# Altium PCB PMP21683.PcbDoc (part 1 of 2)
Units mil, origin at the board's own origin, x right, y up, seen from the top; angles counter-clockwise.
Board outline 4950 x 3450 mil, 2 copper layers (Top Layer, Bottom Layer), stack 62 mil thick; 134 components, 57 nets, 365 pads, 111 vias.
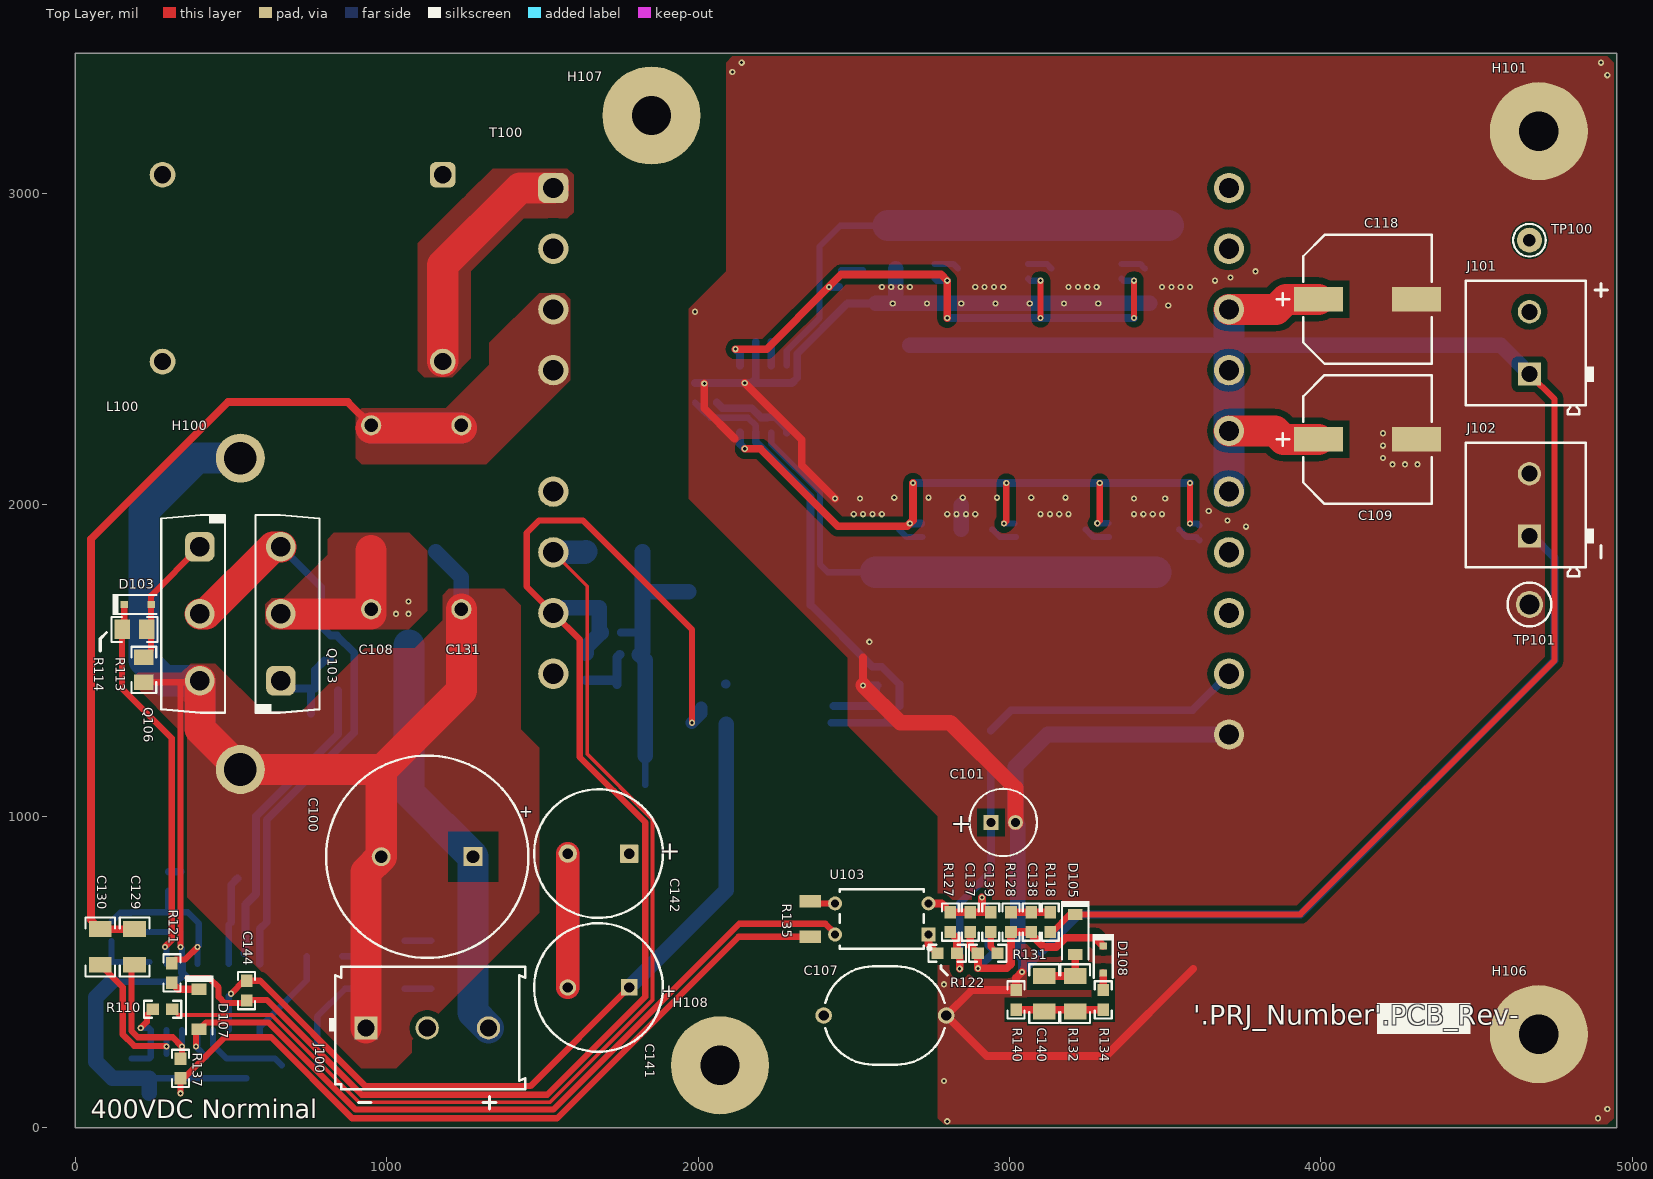
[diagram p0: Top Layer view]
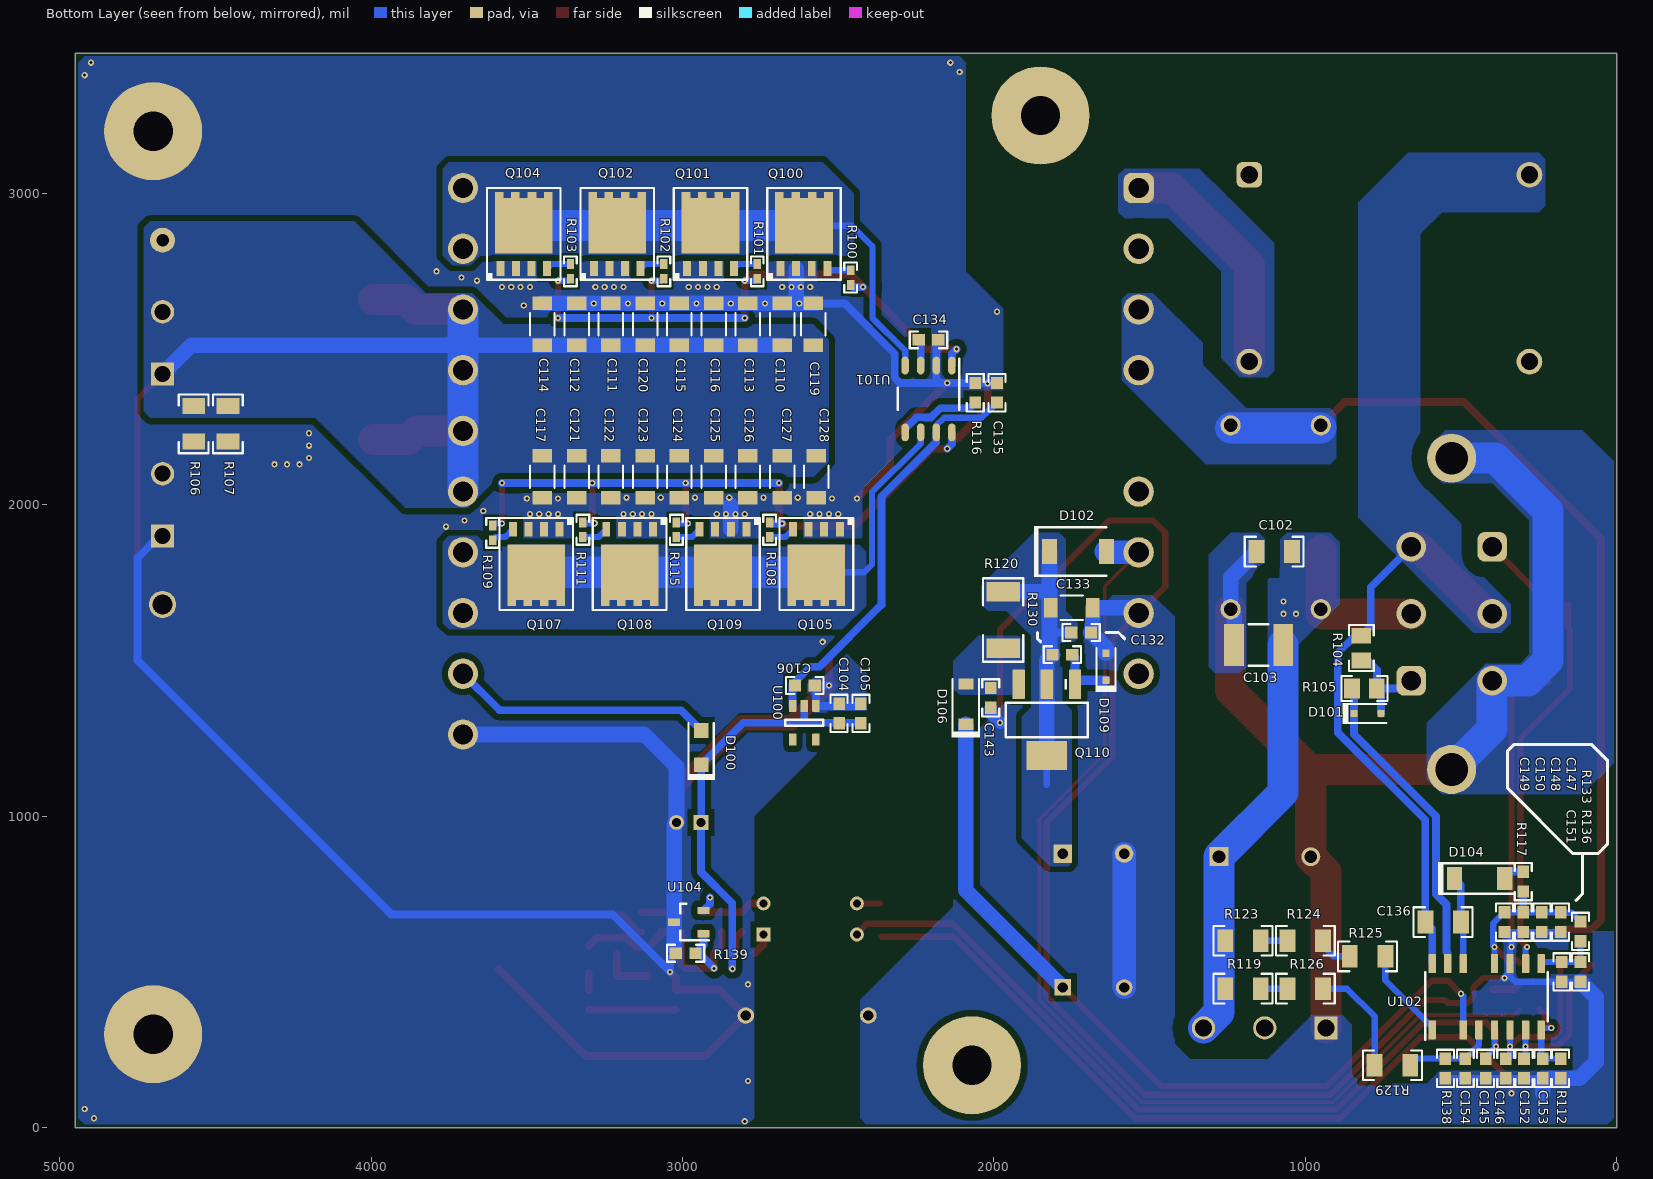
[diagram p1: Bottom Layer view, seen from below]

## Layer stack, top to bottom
Top Solder: solder mask 0.4, Solder Resist, Dk 3.5
Top Layer: signal copper 1.4
Dielectric1: core 59.2, FR-4, Dk 4.8
Bottom Layer: signal copper 1.4
Bottom Solder: solder mask 0.4, Solder Resist, Dk 3.5

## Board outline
0,0 4950,0 4950,3450 0,3450

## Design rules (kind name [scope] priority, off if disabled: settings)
AcuteAngle [All] p1: minimum=4.50000000000000E+0001 checktracksonly=FALSE
AssemblyTestPointUsage [All] p1: valid=2
Clearance Clearance_3 [InNet('GND') vs InNet('SGND')] p1: gap=236 ignorepadtopadclearanceinfootprint=FALSE
Clearance Clearance_2 [InNetClass('HV') vs Not InNetClass('HV')] p2: gap=50 ignorepadtopadclearanceinfootprint=FALSE except(0: Arc-Hole Track-Hole SMDPad-Hole THPad-Hole Via-Hole Fill-Hole Poly-Hole Region-Hole Text-Hole)
Clearance Clearance_1 [InNetClass('MV') vs Not InNetClass('MV')] p3: gap=30 ignorepadtopadclearanceinfootprint=FALSE
Clearance Clearance_Keepouts [((IsTrack Or IsArc) And Not InPoly) And IsFree and IsKeepOut vs ((IsTrack Or IsArc) And Not InPoly) And IsFree and IsKeepOut] p4: gap=0 ignorepadtopadclearanceinfootprint=FALSE
Clearance Clearance_BoardEdge_MountingHoles [OnCopper and InComponentClass('Mounting Holes') vs IsKeepOut] p5: gap=40 ignorepadtopadclearanceinfootprint=FALSE except(0: Arc-Hole Track-Hole SMDPad-Hole THPad-Hole Via-Hole Fill-Hole Poly-Hole Region-Hole Text-Hole)
Clearance Clearance_BoardEdge_Poly [OnCopper and InPoly vs IsKeepOut] p6: gap=25 ignorepadtopadclearanceinfootprint=FALSE except(0: Arc-Hole Track-Hole SMDPad-Hole THPad-Hole Via-Hole Fill-Hole Poly-Hole Region-Hole Text-Hole)
Clearance Clearance_BoardEdge [OnCopper and Not InComponentClass('Logo') and not InComponentClass('FiducialMark') and not InRegion(1000,500,4000,800) and Not IsKeepout vs IsKeepOut] p7: gap=75 ignorepadtopadclearanceinfootprint=FALSE except(0: Arc-Hole Track-Hole SMDPad-Hole THPad-Hole Via-Hole Fill-Hole Poly-Hole Region-Hole Text-Hole)
Clearance Clearance_Poly [InPolygon] p8: gap=20 ignorepadtopadclearanceinfootprint=FALSE except(0: Arc-Hole Track-Hole SMDPad-Hole THPad-Hole Via-Hole Fill-Hole Poly-Hole Region-Hole Text-Hole)
Clearance [All] p9: gap=7.87 ignorepadtopadclearanceinfootprint=FALSE except(0: Arc-Hole Track-Hole SMDPad-Hole THPad-Hole Via-Hole Fill-Hole Poly-Hole Region-Hole Text-Hole)
ComponentClearance ComponentClearance_MountingHoles_FiducialMarks [InComponentClass('Mounting Holes') vs InComponentClass('FiducialMark')] p1: gap=20 collisioncheckmode=3 verticalgap=10 showdistances=FALSE
ComponentClearance ComponentClearance_Shunt [InComponentClass('Header') vs InComponentClass('Shunt')] p2: gap=0 collisioncheckmode=3 verticalgap=0 showdistances=FALSE
ComponentClearance ComponentClearance_Logo [InComponentClass('Logo')] p3: gap=5 collisioncheckmode=3 verticalgap=10 showdistances=FALSE
ComponentClearance ComponentClearance_ScrewToNut [(HasFootprint('NY PMS 440 0025 PH')) vs (HasFootprint('Keystone_1902C'))] p4: gap=20 collisioncheckmode=3 verticalgap=100000 showdistances=FALSE
ComponentClearance ComponentClearance_MountingHoles [InComponentClass('Mounting Holes')] p5: gap=20 collisioncheckmode=3 verticalgap=10 showdistances=FALSE
ComponentClearance ComponentClearance_SmallPassives [HasFootprint('0201*') or HasFootprint('0402*') or HasFootprint('0508') or HasFootprint('0603*') or HasFootprint('0612') or HasFootprint('0805*') or HasFootprint('0815*') or HasFootprint('0830*') or HasFootprint('1206*') or HasFootprint('1210*') or HasFootprint('1808*') or HasFootprint('1812*') or HasFootprint('1825*') or HasFootprint('2010*') or HasFootprint('2220*') or HasFootprint('2225*') or HasFootprint('2512*') or HasFootprint('2728*') or HasFootprint('3518*') vs HasFootprint('0201*') or HasFootprint('0402*') or HasFootprint('0508') or HasFootprint('0603*') or HasFootprint('0612') or HasFootprint('0805*') or HasFootprint('0815*') or HasFootprint('0830*') or HasFootprint('1206*') or HasFootprint('1210*') or HasFootprint('1808*') or HasFootprint('1812*') or HasFootprint('1825*') or HasFootprint('2010*') or HasFootprint('2220*') or HasFootprint('2225*') or HasFootprint('2512*') or HasFootprint('2728*') or HasFootprint('3518*')] p6: gap=20 collisioncheckmode=3 verticalgap=20 showdistances=FALSE
ComponentClearance ComponentClearance_THtoSMT [IsThruComponent vs IsSMTComponent] p7: gap=10 collisioncheckmode=3 verticalgap=10 showdistances=FALSE
ComponentClearance ComponentClearance_THtoTH [IsThruComponent vs IsThruComponent] p8: gap=10 collisioncheckmode=3 verticalgap=10 showdistances=FALSE
ComponentClearance [All] p9: gap=10 collisioncheckmode=3 verticalgap=10 showdistances=FALSE
DiffPairsRouting [All] p1: maxlimit=100 minlimit=10 mostfreqgap=10 toplayer_minwidth=15 toplayer_maxwidth=15 toplayer_prefwidth=15 bottomlayer_minwidth=15 bottomlayer_maxwidth=15 bottomlayer_prefwidth=15 maxuncoupledlength=1000
FabricationTestPointUsage TestPointUsage [All] p1: valid=2 allowmultiple=FALSE
FabricationTestpoint Testpoint [All] p1: side=3 testpointundercomponent=TRUE minsize=40 maxsize=100 preferedsize=60 minholesize=0 maxholesize=40 preferedholesize=32 testpointgrid=1 allowsidetop=TRUE allowsidebottom=TRUE usegrid=TRUE gridtolerance=0.01
FanoutControl Fanout_LCC [IsLCC] p1: bgadir=Out bgaviamode=Centered fanoutstyle=Auto fanoutdirection=Alternating viagrid=1 // Fanout_LCC (Default Rule)
FanoutControl Fanout_BGA [IsBGA] p2: bgadir=Out bgaviamode=Centered fanoutstyle=Auto fanoutdirection=Alternating viagrid=1 // Fanout_BGA (Default Rule)
FanoutControl Fanout_Default [All] p4: bgadir=Out bgaviamode=Centered fanoutstyle=Auto fanoutdirection=Alternating viagrid=1 // Fanout_Default (Default Rule)
FanoutControl Fanout_Small [(CompPinCount < 5)] p5: bgadir=Out bgaviamode=Centered fanoutstyle=Auto fanoutdirection=OutThenIn viagrid=1 // Fanout_Small (Default Rule)
Height [All] p1: minheight=0 maxheight=3000 prefheight=500
HoleSize [All] p1: absolutevalues=TRUE maxlimit=251 minlimit=7 maxpercent=80.000 minpercent=20.000
MinimumAnnularRing MinimumAnnularRing_ThermalPadVias [IsVia and InAnyComponent] p1: minimumring=5.91
MinimumAnnularRing [All] p2: minimumring=4.9
MinimumSolderMaskSliver MinimumSolderMaskSliver_Logo [InComponentClass('Logo') vs InComponentClass('Logo')] p1: minsoldermaskwidth=0.7
MinimumSolderMaskSliver [All] p2: minsoldermaskwidth=2
PlaneConnect [All] p1: planeconnectstyle=Direct reliefexpansion=10 reliefentries=4 reliefconductorwidth=10 reliefairgap=10
PolygonConnect PolygonConnect_17 [All vs IsNamedPolygon('SGND') Or  IsNamedPolygon('VD_SR2') Or  IsNamedPolygon('SGND') Or  IsNamedPolygon('VD_SR1') Or  IsNamedPolygon('Vout') Or  IsNamedPolygon('C141_2') Or  IsNamedPolygon('VCC') Or  IsNamedPolygon('Vin') Or  IsNamedPolygon('L100_4') Or  IsNamedPolygon('C108_2') Or  IsNamedPolygon('L100_4') Or  IsNamedPolygon('HS') Or  IsNamedPolygon('Vin')] p1: connectstyle=Direct reliefconductorwidth=10 reliefentries=4 polygonreliefangle="90 Angle" airgapwidth=10
PolygonConnect PolygonConnect_16 [All vs IsNamedPolygon('HS') Or  IsNamedPolygon('L100_4') Or  IsNamedPolygon('Vin1') Or  IsNamedPolygon('C108_2') Or  IsNamedPolygon('Vin') Or  IsNamedPolygon('VCC') Or  IsNamedPolygon('C141_2') Or  IsNamedPolygon('L100_4') Or  IsNamedPolygon('Vin')] p2: connectstyle=Direct reliefconductorwidth=10 reliefentries=4 polygonreliefangle="90 Angle" airgapwidth=10
PolygonConnect PolygonConnect_15 [All vs IsNamedPolygon('C109_2') Or  IsNamedPolygon('C107_2') Or  IsNamedPolygon('HV') Or  IsNamedPolygon('Q203_5') Or  IsNamedPolygon('C107_2') Or  IsNamedPolygon('HS') Or  IsNamedPolygon('Q201_5') Or  IsNamedPolygon('Q203_5') Or  IsNamedPolygon('C106_2') Or  IsNamedPolygon('C108_2') Or  IsNamedPolygon('Vout') Or  IsNamedPolygon('Q203_5') Or  IsNamedPolygon('C108_2') Or  IsNamedPolygon('C113_2') Or  IsNamedPolygon('Q203_5') Or  IsNamedPolygon('Q201_5') Or  IsNamedPolygon('C107_2') Or  IsNamedPolygon('C102_1') Or  IsNamedPolygon('SGND') Or  IsNamedPolygon('GND') Or  IsNamedPolygon('SGND') Or  IsNamedPolygon('GND') Or  IsNamedPolygon('IN+') Or  IsNamedPolygon('IN+') Or  IsNamedPolygon('Q201_5') Or  IsNamedPolygon('Q201_5') Or  IsNamedPolygon('SGND') Or  IsNamedPolygon('SGND') Or  IsNamedPolygon('Vout') Or  IsNamedPolygon('Vout') Or  IsNamedPolygon('IN+') Or  IsNamedPolygon('GND') Or  IsNamedPolygon('IN+') Or  IsNamedPolygon('GND')] p3: connectstyle=Direct reliefconductorwidth=10 reliefentries=4 polygonreliefangle="90 Angle" airgapwidth=10
PolygonConnect PolygonConnect_14 [All vs IsNamedPolygon('C106_2') Or  IsNamedPolygon('C107_2') Or  IsNamedPolygon('C107_2') Or  IsNamedPolygon('C107_2') Or  IsNamedPolygon('C102_1') Or  IsNamedPolygon('Q203_5') Or  IsNamedPolygon('Vout') Or  IsNamedPolygon('Q203_5') Or  IsNamedPolygon('Q203_5') Or  IsNamedPolygon('Q201_5') Or  IsNamedPolygon('C108_2') Or  IsNamedPolygon('Q203_5') Or  IsNamedPolygon('HS') Or  IsNamedPolygon('HV') Or  IsNamedPolygon('C108_2') Or  IsNamedPolygon('Q201_5') Or  IsNamedPolygon('C109_2') Or  IsNamedPolygon('Q201_5') Or  IsNamedPolygon('Q201_5') Or  IsNamedPolygon('C113_2')] p4: connectstyle=Direct reliefconductorwidth=10 reliefentries=4 polygonreliefangle="90 Angle" airgapwidth=10
PolygonConnect PolygonConnect_13 [All vs IsNamedPolygon('C102_1') Or  IsNamedPolygon('HV') Or  IsNamedPolygon('C107_2') Or  IsNamedPolygon('C109_2') Or  IsNamedPolygon('C107_2') Or  IsNamedPolygon('C108_2') Or  IsNamedPolygon('C106_2') Or  IsNamedPolygon('C108_2') Or  IsNamedPolygon('C113_2') Or  IsNamedPolygon('C107_2')] p5: connectstyle=Direct reliefconductorwidth=10 reliefentries=4 polygonreliefangle="90 Angle" airgapwidth=10
PolygonConnect PolygonConnect_12 [All vs IsNamedPolygon('C107_2') Or  IsNamedPolygon('C113_2') Or  IsNamedPolygon('C106_2') Or  IsNamedPolygon('C107_2') Or  IsNamedPolygon('C107_2') Or  IsNamedPolygon('C102_1')] p6: connectstyle=Direct reliefconductorwidth=10 reliefentries=4 polygonreliefangle="90 Angle" airgapwidth=10
PolygonConnect PolygonConnect_11 [All vs IsNamedPolygon('C106_2') Or  IsNamedPolygon('C102_1') Or  IsNamedPolygon('C107_2') Or  IsNamedPolygon('C107_2') Or  IsNamedPolygon('C107_2')] p7: connectstyle=Direct reliefconductorwidth=10 reliefentries=4 polygonreliefangle="90 Angle" airgapwidth=10
PolygonConnect PolygonConnect_10 [All vs IsNamedPolygon('C106_2')] p8: connectstyle=Direct reliefconductorwidth=10 reliefentries=4 polygonreliefangle="90 Angle" airgapwidth=10
PolygonConnect PolygonConnect_9 [All vs IsNamedPolygon('C11_1') Or  IsNamedPolygon('Vin') Or  IsNamedPolygon('Vin') Or  IsNamedPolygon('5V') Or  IsNamedPolygon('D6_2') Or  IsNamedPolygon('Q3_3') Or  IsNamedPolygon('GND2') Or  IsNamedPolygon('GND2') Or  IsNamedPolygon('GND') Or  IsNamedPolygon('Q3_4') Or  IsNamedPolygon('12V5') Or  IsNamedPolygon('GND') Or  IsNamedPolygon('12V5') Or  IsNamedPolygon('D3_1')] p9: connectstyle=Direct reliefconductorwidth=10 reliefentries=4 polygonreliefangle="90 Angle" airgapwidth=10
PolygonConnect PolygonConnect_8 [All vs IsNamedPolygon('C11_1') Or  IsNamedPolygon('Vin') Or  IsNamedPolygon('12V5') Or  IsNamedPolygon('Q3_3') Or  IsNamedPolygon('GND2') Or  IsNamedPolygon('GND2') Or  IsNamedPolygon('5V') Or  IsNamedPolygon('Q3_4') Or  IsNamedPolygon('12V5')] p10: connectstyle=Direct reliefconductorwidth=10 reliefentries=4 polygonreliefangle="90 Angle" airgapwidth=10
PolygonConnect PolygonConnect_7 [All vs IsNamedPolygon('GND2') Or  IsNamedPolygon('GND2') Or  IsNamedPolygon('5V') Or  IsNamedPolygon('12V5') Or  IsNamedPolygon('12V5') Or  IsNamedPolygon('C11_1')] p11: connectstyle=Direct reliefconductorwidth=10 reliefentries=4 polygonreliefangle="90 Angle" airgapwidth=10
PolygonConnect PolygonConnect_6 [All vs IsNamedPolygon('GND2') Or  IsNamedPolygon('SGND') Or  IsNamedPolygon('GND1') Or  IsNamedPolygon('C901_1') Or  IsNamedPolygon('SGND') Or  IsNamedPolygon('GND2') Or  IsNamedPolygon('GND1')] p12: connectstyle=Direct reliefconductorwidth=10 reliefentries=4 polygonreliefangle="90 Angle" airgapwidth=10
PolygonConnect PolygonConnect_5 [All vs IsNamedPolygon('GND1') Or  IsNamedPolygon('GND1')] p13: connectstyle=Direct reliefconductorwidth=10 reliefentries=4 polygonreliefangle="90 Angle" airgapwidth=10
PolygonConnect PolygonConnect_4 [All vs IsNamedPolygon('C21_1') Or  IsNamedPolygon('C5_1') Or  IsNamedPolygon('C12_2') Or  IsNamedPolygon('C2_2') Or  IsNamedPolygon('C13_1') Or  IsNamedPolygon('C28_1') Or  IsNamedPolygon('C6_1') Or  IsNamedPolygon('GND') Or  IsNamedPolygon('GND2') Or  IsNamedPolygon('C14_1') Or  IsNamedPolygon('C13_1') Or  IsNamedPolygon('Q1_3') Or  IsNamedPolygon('C14_1') Or  IsNamedPolygon('C5_1') Or  IsNamedPolygon('GND2') Or  IsNamedPolygon('C28_1') Or  IsNamedPolygon('D5_2') Or  IsNamedPolygon('D6_2') Or  IsNamedPolygon('D2_1') Or  IsNamedPolygon('C12_2') Or  IsNamedPolygon('D2_1') Or  IsNamedPolygon('C4_1') Or  IsNamedPolygon('C4_1') Or  IsNamedPolygon('C2_2') Or  IsNamedPolygon('GND') Or  IsNamedPolygon('C33_1') Or  IsNamedPolygon('C9_1')] p14: connectstyle=Direct reliefconductorwidth=10 reliefentries=4 polygonreliefangle="90 Angle" airgapwidth=10
PolygonConnect PolygonConnect_3 [All vs IsNamedPolygon('C28_1') Or  IsNamedPolygon('C12_2') Or  IsNamedPolygon('C28_1') Or  IsNamedPolygon('C9_1') Or  IsNamedPolygon('D5_2') Or  IsNamedPolygon('C12_2') Or  IsNamedPolygon('C2_2') Or  IsNamedPolygon('C14_1') Or  IsNamedPolygon('C4_1') Or  IsNamedPolygon('C14_1') Or  IsNamedPolygon('D6_2') Or  IsNamedPolygon('GND2') Or  IsNamedPolygon('Q1_3') Or  IsNamedPolygon('C5_1') Or  IsNamedPolygon('D2_1') Or  IsNamedPolygon('C4_1') Or  IsNamedPolygon('C13_1') Or  IsNamedPolygon('C5_1') Or  IsNamedPolygon('C13_1') Or  IsNamedPolygon('C33_1') Or  IsNamedPolygon('D2_1') Or  IsNamedPolygon('GND') Or  IsNamedPolygon('GND') Or  IsNamedPolygon('GND2') Or  IsNamedPolygon('C2_2') Or  IsNamedPolygon('C6_1') Or  IsNamedPolygon('C21_1')] p15: connectstyle=Direct reliefconductorwidth=10 reliefentries=4 polygonreliefangle="90 Angle" airgapwidth=10
PolygonConnect PolygonConnect_2 [All vs IsNamedPolygon('C21_1') Or  IsNamedPolygon('C4_1') Or  IsNamedPolygon('D5_2') Or  IsNamedPolygon('C5_1') Or  IsNamedPolygon('C14_1') Or  IsNamedPolygon('C13_1') Or  IsNamedPolygon('C4_1') Or  IsNamedPolygon('C33_1') Or  IsNamedPolygon('C12_2') Or  IsNamedPolygon('D2_1') Or  IsNamedPolygon('C2_2') Or  IsNamedPolygon('C28_1') Or  IsNamedPolygon('C12_2') Or  IsNamedPolygon('D2_1') Or  IsNamedPolygon('C5_1') Or  IsNamedPolygon('Q1_3') Or  IsNamedPolygon('GND') Or  IsNamedPolygon('D6_2') Or  IsNamedPolygon('C6_1') Or  IsNamedPolygon('C2_2') Or  IsNamedPolygon('C14_1') Or  IsNamedPolygon('C28_1') Or  IsNamedPolygon('C13_1') Or  IsNamedPolygon('C9_1') Or  IsNamedPolygon('GND')] p16: connectstyle=Direct reliefconductorwidth=10 reliefentries=4 polygonreliefangle="90 Angle" airgapwidth=10
PolygonConnect PolygonConnect_1 [All vs IsNamedPolygon('C28_1') Or  IsNamedPolygon('D5_2') Or  IsNamedPolygon('C5_1') Or  IsNamedPolygon('C5_1') Or  IsNamedPolygon('D2_1') Or  IsNamedPolygon('C21_1') Or  IsNamedPolygon('C9_1') Or  IsNamedPolygon('C4_1') Or  IsNamedPolygon('C14_1') Or  IsNamedPolygon('C28_1') Or  IsNamedPolygon('C6_1') Or  IsNamedPolygon('C12_2') Or  IsNamedPolygon('C33_1') Or  IsNamedPolygon('C4_1') Or  IsNamedPolygon('C13_1') Or  IsNamedPolygon('C12_2') Or  IsNamedPolygon('D6_2') Or  IsNamedPolygon('C2_2') Or  IsNamedPolygon('C14_1') Or  IsNamedPolygon('D2_1') Or  IsNamedPolygon('C2_2') Or  IsNamedPolygon('C13_1')] p17: connectstyle=Direct reliefconductorwidth=10 reliefentries=4 polygonreliefangle="90 Angle" airgapwidth=10
PolygonConnect [All] p18: connectstyle=Relief reliefconductorwidth=10 reliefentries=4 polygonreliefangle="90 Angle" airgapwidth=10
RoutingVias ThermalPadVias [IsVia and InAnyComponent] p1: holewidth=7.87 width=19.68 viastyle="Through Hole" minholewidth=7.87 minwidth=19.68 maxholewidth=12.99 maxwidth=23.62
RoutingVias [All] p2: holewidth=16 width=34 viastyle="Through Hole" minholewidth=7.87 minwidth=20 maxholewidth=40 maxwidth=65
SilkToBoardRegionClearance [Not ((IsComment or IsDesignator) And (Hide <> 'False')) and not InRegion(1000,500,4000,800)] p1:
SilkToSilkClearance SilkToSilkClearance_Pb-FreeLogo [(HasFootprint('Pb-Free_Overlay_Medium') OR HasFootprint('Pb-Free_Overlay_Small')) vs (HasFootprint('Pb-Free_Overlay_Medium') OR HasFootprint('Pb-Free_Overlay_Small'))] p1: silktosilkclearance=0
SilkToSilkClearance [All] p2: silktosilkclearance=1
SilkToSolderMaskClearance "Silk to Solder Mask Opening" [All] p1: minsilkscreentomaskgap=1 clearancetoexposedcopper=FALSE
SolderMaskExpansion [All] p1: expansion=1.97
Width [All] p1: maxlimit=100 minlimit=6 preferedwidth=10 checkconnectedcopper=TRUE
14 further rules are at their usual default settings.

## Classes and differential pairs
net class MV: NetR119_1 NetR123_1 NetR124_1 NetR126_1
net class HV: HO HS NetC108_2 NetC136_1 NetD101_2 NetL100_4 VIN
component class "Mounting Holes": H101 H106 H107 H108

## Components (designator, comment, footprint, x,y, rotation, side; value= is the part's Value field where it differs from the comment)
C100 "860241480001" VR_1600x2500 1130,870 r180 top value=100uF
C101 "25ML22MEFC5X5" ML_500x500 2980,980 r0 top value=22uF
C102 "GRM31BR72J103KW01L" 1206 1100,1850 r0 bottom value=0.01uF
C103 "C1812W104KDRACTU" 1812_254 1150,1550 r0 bottom value=0.1uF
C104 "GRM188R6YA225KA12D" 0603 2497.2,1330 r270 bottom value=2.2uF
C105 "06033C104JAT2A" 0603 2427.2,1330 r270 bottom value=0.1uF
C106 "GRM185R61A105KE36D" 0603 2607.2,1420 r180 bottom value=1uF
C107 "DE1E3KX222MA5BA01" CAPRD1000W60D1000H1400 2600,360 r180 top value=2200pF
C108 "890303325004CS" WCAP-FTBP_1800x600x1200 950,1960 r90 top value=0.068uF
C109 "PCR1J101MCL1GS" CR_1000x1270 4150,2210 r0 top value=100uF
C110 "GRM31CR72A225KA73L" 1206_190 2680,2580 r90 bottom value=2.2uF
C111 "GRM31CR72A225KA73L" 1206_190 3230,2580 r90 bottom value=2.2uF
C112 "GRM31CR72A225KA73L" 1206_190 3340,2580 r90 bottom value=2.2uF
C113 "GRM31CR72A225KA73L" 1206_190 2790,2580 r90 bottom value=2.2uF
C114 "GRM31CR72A225KA73L" 1206_190 3450,2580 r90 bottom value=2.2uF
C115 "GRM31CR72A225KA73L" 1206_190 3010,2580 r90 bottom value=2.2uF
C116 "GRM31CR72A225KA73L" 1206_190 2900,2580 r90 bottom value=2.2uF
C117 "GRM31CR72A225KA73L" 1206_190 3450,2090 r270 bottom value=2.2uF
C118 "PCR1J101MCL1GS" CR_1000x1270 4150,2660 r0 top value=100uF
C119 "GRM31CR72A225KA73L" 1206_190 2580,2580 r270 bottom value=2.2uF
C120 "GRM31CR72A225KA73L" 1206_190 3120,2580 r270 bottom value=2.2uF
C121 "GRM31CR72A225KA73L" 1206_190 3340,2090 r90 bottom value=2.2uF
C122 "GRM31CR72A225KA73L" 1206_190 3230,2090 r90 bottom value=2.2uF
C123 "GRM31CR72A225KA73L" 1206_190 3120,2090 r90 bottom value=2.2uF
C124 "GRM31CR72A225KA73L" 1206_190 3010,2090 r90 bottom value=2.2uF
C125 "GRM31CR72A225KA73L" 1206_190 2900,2090 r90 bottom value=2.2uF
C126 "GRM31CR72A225KA73L" 1206_190 2790,2090 r90 bottom value=2.2uF
C127 "GRM31CR72A225KA73L" 1206_190 2680,2090 r90 bottom value=2.2uF
C128 "GRM31CR72A225KA73L" 1206_190 2570,2090 r90 bottom value=2.2uF
C129 "GRM31A7U3A151JW31D" 1206 190,580 r270 top value=150pF
C130 "GRM31A7U3A151JW31D" 1206 80,580 r270 top value=150pF
C131 "890303325004CS" WCAP-FTBP_1800x600x1200 1240,1960 r270 top value=0.068uF
C132 "GRM188R6YA225KA12D" 0603 1720,1590 r0 bottom value=2.2uF
C133 "C3216X5R1H225K160AB" 1206_180 1750,1670 r180 bottom value=2.2uF
C134 "885012106018" 0603 2210,2530 r0 bottom value=2.2uF
C135 "C0603C225K9PACTU" 0603 1990,2360 r90 bottom value=2.2uF
C136 "C1206C225K4RACTU" 1206 557.5,660 r0 bottom value=2.2uF
C137 "06035A101JAT2A" 0603 2874.21,660 r270 top value=100pF
C138 "06035A101JAT2A" 0603 3070,660 r90 top value=100pF
C139 "06033C473JAT2A" 0603 2940,660 r90 top value=0.047uF
C140 "GRM319R72A104KA01D" 1206 3111.3,430 r270 top value=0.1uF
C141 "860080575012" KL_1000x2000 1680,450 r180 top value=220uF
C142 "860040575012" HW_1000x2000 1680,880 r180 top value=680uF
C143 "GRM188R6YA225KA12D" 0603 2010,1380 r90 bottom value=2.2uF
C144 "GRM188R6YA225KA12D" 0603 550,440 r90 top value=2.2uF
C145 "GRM1885C1H470FA01J" 0603 420.93,190 r270 bottom value=47pF
C146 "06031C331JAT2A" 0603 356.18,190 r270 bottom value=330pF
C147 "GRM188R61C475KAAJ" 0603 180,660 r270 bottom value=4.7uF
C148 "GRM188R61C475KAAJ" 0603 240,660 r270 bottom value=4.7uF
C149 "GRM188R61C475KAAJ" 0603 360,660 r270 bottom value=4.7uF
C150 "06031C103JAT2A" 0603 300,660 r270 bottom value=0.01uF
C151 "0603YC104JAT2A" 0603 176.04,500 r270 bottom value=0.1uF
C152 "06031C682KAT2A" 0603 297.5,190 r270 bottom value=6800pF
C153 "06035A2R2CAT2A" 0603 237.5,190 r270 bottom value=2.2pF
C154 "GRM188R71H221KA01D" 0603 486.04,190 r270 bottom value=220pF
D100 "BAT46WH,115" SOD-123F 2940,1220 r90 bottom value=100V
D101 "MMDL914-TP" SOD-323 800,1330 r180 bottom value=100V
D102 "STPS2200UF" SMB_flat 1730,1850 r180 bottom value=200V
D103 "MMDL914-TP" SOD-323 200,1680 r0 top value=100V
D104 "ES1JAF" SMAF 440,800 r180 bottom value=600V
D105 "MMSZ5257B-7-F" SOD-123 3211.3,620 r270 top value=33V
D106 "1N4148W-7-F" SOD-123 2090,1360 r90 bottom value=100V
D107 "MMSZ5234B-7-F" SOD-123 397.5,380 r270 top value=6.2V
D108 "MMDL914-TP" SOD-323 3301.3,540 r270 top value=100V
D109 "MMSZ5250BS-7-F" SOD-323 1640,1480 r90 bottom value=20V
H100 "513002B02500G" Aavid_513002B02500G 530,1650 r270 top
H101 "NY PMS 440 0025 PH" "NY PMS 440 0025 PH" 4700,3200 r0 top
H106 "NY PMS 440 0025 PH" "NY PMS 440 0025 PH" 4700,300 r0 top
H107 "NY PMS 440 0025 PH" "NY PMS 440 0025 PH" 1850,3250 r0 top
H108 "NY PMS 440 0025 PH" "NY PMS 440 0025 PH" 2070,200 r0 top
J100 "282856-3" TE_282856-3 1130,320 r0 top
J101 "1715721" PhoenixContact_1715721 4670,2520 r90 top
J102 "1715721" PhoenixContact_1715721 4670,2000 r90 top
L100 "RLTI-1304" RLTI-1304 730,2760 r270 top
Q100 "BSC320N20NS3 G" PG-TDSON-8 2610,2870 r90 bottom value=200V
Q101 "BSC320N20NS3 G" PG-TDSON-8 2910,2870 r90 bottom value=200V
Q102 "BSC320N20NS3 G" PG-TDSON-8 3210,2870 r90 bottom value=200V
Q103 "IPW60R075CPFKSA1" TO-247 660,1650 r90 top value=600V
Q104 "BSC320N20NS3 G" PG-TDSON-8 3510,2870 r90 bottom value=200V
Q105 "BSC320N20NS3 G" PG-TDSON-8 2570,1810 r270 bottom value=200V
Q106 "IPW60R075CPFKSA1" TO-247 400,1650 r270 top value=600V
Q107 "BSC320N20NS3 G" PG-TDSON-8 3470,1810 r270 bottom value=200V
Q108 "BSC320N20NS3 G" PG-TDSON-8 3170,1810 r270 bottom value=200V
Q109 "BSC320N20NS3 G" PG-TDSON-8 2870,1810 r270 bottom value=200V
Q110 "FZT651TA" SOT-223 1830,1309.19 r270 bottom value="60 V"
R100 "CRCW04023R00JNED" 0402 2460,2730 r270 bottom value=3.0
R101 "CRCW04023R00JNED" 0402 2760,2750 r270 bottom value=3.0
R102 "CRCW04023R00JNED" 0402 3060,2750 r270 bottom value=3.0
R103 "CRCW04023R00JNED" 0402 3360,2750 r270 bottom value=3.0
R104 "RG2012P-103-B-T5" 0805_HV 820,1540 r270 bottom value=10.0k
R105 "RC0805JR-0710RL" 0805_HV 810,1410 r180 bottom value=10
R106 "CRCW120649K9FKEA" 1206 4570,2260 r270 bottom value=49.9k
R107 "CRCW120649K9FKEA" 1206 4460,2260 r270 bottom value=49.9k
R108 "CRCW04023R00JNED" 0402 2720,1920 r90 bottom value=3.0
R109 "CRCW04023R00JNED" 0402 3610,1910 r90 bottom value=3.0
R110 "CRCW060351K1FKEA" 0603 280,380 r0 top value=51.1k
R111 "CRCW04023R00JNED" 0402 3320,1920 r90 bottom value=3.0
R112 "RCG060310K0FKEA" 0603 180,190 r90 bottom value=10.0k
R113 "RG2012P-103-B-T5" 0805_HV 220,1470 r90 top value=10.0k
R114 "RC0805JR-0710RL" 0805_HV 190,1600 r0 top value=10
R115 "CRCW04023R00JNED" 0402 3020,1920 r90 bottom value=3.0
R116 "RMCF0603ZT0R00" 0603 2060,2360 r90 bottom value=0
R117 "CRCW06032R20JNEA" 0603 300,790 r90 bottom value=2.2
R118 "CRCW060320R0FKEA" 0603 3131.3,660 r90 top value=20.0
R119 "CRCW12064M99FKEA" 1206 1200,446.26 r0 bottom value=4.99Meg
R120 "CRCW20100000Z0EF" 2010 1970,1630 r270 bottom value=0
R121 "ERJ-3EKF1002V" 0603 310,496.7 r90 top value=10.0k
R122 "RG1608P-1581-B-T5" 0603 2800,560 r0 top value=1.58k
R123 "CRCW12061K65FKEA" 1206 1200,600 r0 bottom value=1.65k
R124 "CRCW12061K65FKEA" 1206 1000,600 r0 bottom value=1.65k
R125 "CRCW12061K65FKEA" 1206 800,550 r0 bottom value=1.65k
R126 "CRCW12064M99FKEA" 1206 1000,446.26 r0 bottom value=4.99Meg
R127 "CRCW06036K04FKEA" 0603 2810,660 r270 top value=6.04k
R128 "CRCW0603383KFKEA" 0603 3005,660 r90 top value=383k
R129 "CRCW12064M99FKEA" 1206 720,200 r0 bottom value=4.99Meg
R130 "CRCW060310K0FKEA" 0603 1779.98,1518.88 r0 bottom value=10.0k
R131 "CRCW060310K0FKEA" 0603 2930,560 r180 top value=10.0k
R132 "CRCW12061M00FKEA" 1206 3211.3,430 r90 top value=1.00Meg
R133 "CRCW0603590KFKEA" 0603 116.04,630 r90 bottom value=590k
R134 "RC0603FR-0720KL" 0603 3301.3,410 r270 top value=20.0k
R135 "5108" 5108 2360,670 r90 top value=0
R136 "CRCW0603412KFKEA" 0603 116.04,500 r90 bottom value=412k
R137 "CRCW060368R1FKEA" 0603 337.5,190 r90 top value=68.1
R138 "CRCW060357K6FKEA" 0603 550,190 r90 bottom value=57.6k
R139 "RCG060310K0FKEA" 0603 2989.98,560 r180 bottom value=10.0k
R140 "CRCW060351K1FKEA" 0603 3021.3,410 r270 top value=51.1k
T100 "RLTI-1303" Renco_RLTI-1303 2620,2140 r0 top value=250uH
TP100 "5000" Keystone5000 4670,2850 r90 top
TP101 "5011" Keystone5011 4670,1680 r90 top
U100 "TLV70450DBVR" DBV0005A_N 2609.05,1300.16 r270 bottom
U101 "UCC24624DR" D0008A_N 2210,2340 r270 bottom
U102 "UCC256302DDB" DDB0014A 417.5,420 r90 bottom
U103 "VO618A-3" DIP-4 2590,670 r180 top
U104 "TLVH431AQDBZR" DBZ0003A_N 2980,660 r0 bottom

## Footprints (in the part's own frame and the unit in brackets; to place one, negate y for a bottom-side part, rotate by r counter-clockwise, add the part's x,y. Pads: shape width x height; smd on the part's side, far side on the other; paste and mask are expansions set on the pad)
0402 [mm] "0402 from SM-752 data"
  rect 0.8x0.6 smd: 1(-0.6,0) 2(0.6,0)
  silkscreen extent -1.22,-0.52 1.22,0.52, body extent -0.55,-0.3 0.55,0.3, height 0.6
0603 [mm] "0603 from SM-752 data"
  rect 1x0.95 smd: 1(-0.8,0) 2(0.8,0)
  silkscreen extent -1.52,-0.69 1.52,0.69, body extent -0.87,-0.47 0.87,0.47, height 1
0805_HV [mil] "0805 with 30mil clearance between pads"
  rect 50x63 smd: 1(-40,0) 2(40,0)
  silkscreen extent -74,-40 74,40, body extent -43,-29 43,29, height 57
1206 [mm] "1206 from SM-752 data"
  rect 1.3x1.85 smd: 1(-1.45,0) 2(1.45,0)
  silkscreen extent -2.4,-1.21 2.4,1.21, body extent -1.7,-0.9 1.7,0.9, height 1.35
1206_180 [mm] "1206_180"
  rect 1.1x1.6 smd: 1(-1.7,0) 2(1.7,0)
  silkscreen extent -0.9,-1 0.9,1, body extent -1.75,-0.95 1.75,0.95, height 1.8
1206_190 [mm] "1206_190"
  rect 1.1x1.6 smd: 1(-1.7,0) 2(1.7,0)
  silkscreen extent -0.9,-1 0.9,1, body extent -1.75,-0.95 1.75,0.95, height 1.9
1812_254 [mm] "SMD, 2-Leads, Body 4.8x3.4mm"
  rect 1.6x3.4 smd: 1(-2,0) 2(2,0)
  silkscreen extent -0.8,-1.7 0.8,1.7, body extent -2.4,-1.7 2.4,1.7, height 2.54
2010 [mm] "Chip Capacitor, Body 5.08x2.54mm, IPC Medium Density"
  rect 1.6x2.7 smd: 1(-2.3,0) 2(2.3,0)
  silkscreen extent -3.42,-1.65 3.42,1.65, body extent -2.73,-1.45 2.73,1.45, height 1.66
5108 [mm] "Keystone"
  rect 1.01x1.73 smd: 1(-1.445,0) 2(1.445,0)
  body extent -1.52,-0.85 1.52,0.85, height 0.71
Aavid_513002B02500G [mm] "HEATSINK TO-220 W/PINS 1\" TALL"
  round 4.005 hole 2.67: 1(-12.7,0) 2(12.7,0)
  body extent -17.46,-6.35 17.46,6.35, height 25.4
CAPRD1000W60D1000H1400 [mm] "Disk, Radial Capacitor"
  round 1.35 hole 0.85: 1(-5,0) 2(5,0)
  silkscreen extent -4.86,-4 4.86,4, body extent -5.67,-4 5.7,4, height 13.99
CR_1000x1270 [mm] "SMD, 2-Leads, Dia 10.5mm, Pin Spacing 8mm"
  rect 4x2 smd: 1(-4,0) 2(4,0)
  silkscreen extent -7.4,-5.25 5.25,5.25, body extent -5.25,-5.25 5.25,5.25, height 12.71
D0008A_N [mm] "SOIC, 8-Leads, Body 4.9x3.9mm, Pitch 1.27mm, IPC Medium Density"
  oval 1.45x0.6 smd: 1(-2.725,1.905) 2(-2.725,0.635) 3(-2.725,-0.635) 4(-2.725,-1.905) 5(2.725,-1.905) 6(2.725,-0.635) 7(2.725,0.635) 8(2.725,1.905)
  silkscreen extent -3.3,-2.5 0.9,2.5, body extent -3,-2.45 3,2.45, height 1.63
DBV0005A_N [mm] "SOT23, 5-Leads, Body 2.9x1.6mm, Pitch 0.95mm, Lead Span 2.8mm, IPC Medium Density"
  rrect17% 1x0.6 smd: 1(-1.375,0.95) 2(-1.375,0) 3(-1.375,-0.95) 4(1.375,-0.95) 5(1.375,0.95)
  silkscreen extent -0.25,-1.55 0.25,1.55, body extent -1.42,-1.46 1.42,1.46, height 1.09
DBZ0003A_N [mm] "SOT23, 3-Leads, Body 2.9x1.3mm, Pitch 0.95mm, Lead Span 2.4mm, IPC Medium Density"
  rrect17% 1x0.6 smd: 1(-1.2,0.95) 2(-1.2,-0.95) 3(1.2,0)
  silkscreen extent -1.65,-1.5 0.7,1.5, body extent -1.26,-1.46 1.26,1.46, height 0.98
DDB0014A [mm] "SMD, 14-Leads, Body 3.9x9.9mm, Pitch 1.27mm"
  rrect17% 1.55x0.6 smd: 1(-2.7,4.445) 3(-2.7,1.905) 4(-2.7,0.635) 5(-2.7,-0.635) 6(-2.7,-1.905) 7(-2.7,-3.175) 8(-2.7,-4.445) 9(2.7,-4.445) 10(2.7,-3.175) 11(2.7,-1.905) 12(2.7,-0.635) 14(2.7,1.905) 15(2.7,3.175) 16(2.7,4.445)
  silkscreen extent -3.5,-5 2,5, body extent -3.01,-4.95 3.01,4.95, height 1.75
DIP-4 [mm] "DIP, 4-Leads, Body 6.86x4.83mm, Pitch 2.54mm"
  rect 1.15x1.15 hole 0.65: 1(-3.81,1.27)
  round 1.15 hole 0.65: 2(-3.81,-1.27) 3(3.81,-1.27) 4(3.81,1.27)
  silkscreen extent -4,-2.41 3.43,2.52, body extent -4.02,-2.41 4.02,2.41, height 5.59
HW_1000x2000 [mm] "TH, 2-Leads, 10.5x22mm, Pin Spacing 5mm"
  rrect7% 1.5x1.5 hole 0.85: 1(-2.5,0)
  round 1.5 hole 0.85: 2(2.5,0)
  silkscreen extent -5.25,-5.25 5.25,5.25, body extent -5.21,-5.24 5.24,5.24, height 22.01
Keystone5000 [mil] "For Keystone 500x miniature loop terminals"
  round 80 hole 40: 1(0,0)
  silkscreen extent -52,-52 52,52, body extent -49,-49 49,49, height 182
Keystone5011 [mil] "Keystone Multipurpose loops"
  round 87 hole 63: 1(0,0)
  silkscreen extent -70,-70 70,70, body extent -63,-63 63,62, height 319
KL_1000x2000 [mm] "TH, 2-Leads, Dia 10mm, Pin Spacing 5mm"
  rect 1.35x1.35 hole 0.85: 1(-2.5,0)
  round 1.35 hole 0.85: 2(2.5,0)
  silkscreen extent -5.25,-5.25 5.25,5.25, body extent -5.25,-5.25 5.26,5.25, height 21.51
ML_500x500 [mm] "Rubycon"
  rect 1.2x1.2 hole 0.711: 1(-1,0)
  round 1.2 hole 0.711: 2(1,0)
  silkscreen extent -2.75,-2.75 2.75,2.75, body extent -2.73,-2.75 2.75,2.75, height 6.51
"NY PMS 440 0025 PH" [mm] "4-40 nylon screw and mounting hole"
  round 8 hole 3.2: 1(0,0)
  body extent -3.3,-3.3 3.3,3.3, height 2.69
PG-TDSON-8 [mm] "Infineon recommended land pattern"
  rect 1.2x0.65 smd: 1(-2.825,1.905) 2(-2.825,0.635) 3(-2.825,-0.635) 4(-2.825,-1.905)
  rect 0.5x0.7 smd: 5(3.175,-2) 6(3.175,-0.675) 7(3.175,0.675) 8(3.175,2)
  rect 4.5x4.7 smd paste-2.25: 9(0.675,0)
  silkscreen extent -3.74,-3 3.74,3, body extent -3.17,-2.89 3.17,2.9, height 1.1
PhoenixContact_1715721 [mm] "Phoenix Contact 1715721 used on LM3445 design from Longmont"
  rrect5% 1.905x1.905 hole 1.3: 1(-2.54,0)
  round 1.9 hole 1.3: 2(2.54,0)
  silkscreen extent -5.82,-5.25 5.08,5.2, body extent -5.82,-4.6 5.08,5.2, height 14.2
Renco_RLTI-1303 [mm] "TH, 20-Leads, Body 2450x2050mil, Pitch 195mil"
  rrect50% 2.475x2.475 hole 1.65: 1(-27.559,22.288)
  round 2.475 hole 1.65: 2(-27.559,17.335) 3(-27.559,12.383) 4(-27.559,7.429) 6(-27.559,-2.476) 7(-27.559,-7.429) 8(-27.559,-12.383) 9(-27.559,-17.335) 11(27.559,-22.288) 12(27.559,-17.335) 13(27.559,-12.383) 14(27.559,-7.429) 15(27.559,-2.476) 16(27.559,2.476) 17(27.559,7.429) 18(27.559,12.383) 19(27.559,17.335) 20(27.559,22.288)
  body extent -31.11,-26.03 31.12,26.04, height 25.4
RLTI-1304 [mm] "TH, 4-Leads, Dia 1250mil"
  rrect50% 2.1x2.1 hole 1.4: 1(-7.62,11.43)
  round 2.1 hole 1.4: 2(-7.62,-11.43) 3(7.62,-11.43) 4(7.62,11.43)
  body extent -10.29,-15.87 10.29,15.87, height 32.56
SMAF [mm] "SMD, 2-Leads, Body 3.8x2.5mm"
  rect 1.24x1.89 smd: 1(-2.04,0) 2(2.04,0)
  silkscreen extent -3.4,-1.3 2.8,1.3, body extent -2.35,-1.25 2.35,1.25, height 1
SMB_flat [mm] "SMD, 2-Leads, Body 3.625x4.325mm"
  rect 1.2x2.07 smd: 1(-2.32,0) 2(2.32,0)
  silkscreen extent -3.6,-2.07 2.3,2.07, body extent -2.3,-2 2.3,1.97, height 1.1
SOD-123 [mm] "On Semi recommended land pattern"
  rect 0.915x1.22 smd: 1(-1.637,0) 2(1.637,0)
  silkscreen extent -2.74,-1.17 2.03,1.17, body extent -1.93,-0.9 1.93,0.9, height 1.35
SOD-123F [mm] "NXP recommended land pattern"
  rect 1.2x1.2 smd paste-0.05: 1(-1.4,0) 2(1.4,0)
  silkscreen extent -2.64,-1.12 2.01,1.12, body extent -1.8,-0.85 1.8,0.85, height 1.2
SOD-323 [mm] "NXP recommended land pattern"
  rect 0.6x0.6 smd paste-0.05: 1(-1.1,0) 2(1.1,0)
  silkscreen extent -2.06,-0.86 1.53,0.86, body extent -1.3,-0.67 1.3,0.68, height 1.1
SOT-223 [mm] "SOT223/SC73, 4-Leads, Body 6.5x3.5mm, Pitch 2.3mm, Lead Span 7mm, IPC Medium Density"
  rrect10% 2.4x1 smd: 1(-2.9,2.3) 2(-2.9,0) 3(-2.9,-2.3)
  rrect4% 2.4x3.3 smd: 4(2.9,0)
  silkscreen extent -3.32,-3.35 1.4,3.35, body extent -3.5,-3.25 3.5,3.25, height 1.62
TE_282856-3 [mm] "Receptacle, 3x1, 5mm, R/A, TH"
  rect 1.9x1.9 hole 1.4: 1(-5,0)
  round 1.9 hole 1.4: 2(0,0) 3(5,0)
  silkscreen extent -8,-5 8,5, body extent -7.5,-5 8,5, height 19
TO-247 [mil] "Standard TO-247"
  rrect50% 95x95 / inner round 78 / far side rrect50% 95x95 hole 62: 1(-215,0)
  round 95 / inner round 78 / far side round 95 hole 62: 2(0,0) 3(215,0)
  silkscreen extent -318,-124 318,81, body extent -318,-124 318,81, height 1007
VR_1600x2500 [mm] "TH, 2-Leads, Dia 16mm, Pin Spacing 7.5mm"
  rect 1.55x1.55 hole 1.05: 1(-3.75,0)
  round 1.55 hole 1.05: 2(3.75,0)
  silkscreen extent -8.25,-8.25 8.25,8.25, body extent -8.19,-8.24 8.23,8.24, height 27.01
WCAP-FTBP_1800x600x1200 [mm] "TH, 2-Leads, Body 18x6mm, Lead Spacing 15mm"
  round 1.65 hole 1.1: 1(-7.5,0) 2(7.5,0)
  body extent -9.75,-3.5 9.75,3.5, height 12.99

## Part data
C100: library part UVR2A471MHD, "CAP ALUM 100UF 20% 450V RADIAL", Cap_Case=16x25mm, MANUFACTURER=Wurth, Tolerance_%=20, Value2=450V, ValueDisplayed=100µF
C101: "CAP, AL, 22 µF, 25 V, +/- 20%, TH", Cap_Case=5x5, MANUFACTURER=Rubycon, Supplier Part Number 1=25ML22MEFC5X5-ND, Tolerance_%=20, Value2=25V, ValueDisplayed=22µF
C102: "CAP, CERM, 0.01uF, 630V, +/-10%, X7R, 1206", Cap_Case=1206, MANUFACTURER=MuRata, Supplier Part Number 1=490-3512-1-ND, TempCo=X7R, Tolerance_%=10, Value1=Unknown, Value2=630V, ValueDisplayed=0.01µF
C103: "CAP, CERM, 0.1 µF, 1000 V, +/- 10%, X7R, 1812", Cap_Case=1812, MANUFACTURER=Kemet, Supplier Part Number 1=399-6523-1-ND, TempCo=X7R, Tolerance_%=10, Value1=Unknown, Value2=1000V, ValueDisplayed=0.1µF
C104 C132 C143 C144: "CAP, CERM, 2.2 µF, 35 V, +/- 10%, X5R, 0603", Cap_Case=0603, MANUFACTURER=MuRata, Supplier Part Number 1=490-7204-6-ND, TempCo=X5R, Tolerance_%=10, Value1=Unknown, Value2=35V, ValueDisplayed=2.2µF
C105: "CAP, CERM, 0.1 µF, 25 V,+/- 5%, X7R, 0603", Cap_Case=0603, MANUFACTURER=AVX, Supplier Part Number 1=478-3713-1-ND, TempCo=X7R, Tolerance_%=5, Value1="0.05 ohm", Value2=25V, ValueDisplayed=0.1µF
C106: "CAP, CERM, 1 µF, 10 V,+/- 10%, X5R, 0603", Cap_Case=0603, MANUFACTURER=MuRata, Supplier Part Number 1=490-3893-1-ND, TempCo=X5R, Tolerance_%=10, Value2=10V, ValueDisplayed=1µF
C107: library part CMP-0009602-2, "CAP, CERM, 2200 pF, 250 V, +/- 20%, E, Disc 10x8mm", Cap_Case=CAPRD1000W60D1000H1400, MANUFACTURER=MuRata, Supplier Part Number 1=490-7048-ND, TempCo=E, Tolerance_%=20%, Value1=Unknown, Value2=250V, ValueDisplayed=2200pF
C108 C131: library part CMP-0085305-1, "CAP, Film, 0.068 µF, 630 V,+/- 5%, 0.10518 ohm, TH", Cap_Case=18x6x12mm, MANUFACTURER="Wurth Elektronik", Tolerance_%=5%, Value1="0.10518 ohm", Value2=630V, ValueDisplayed=0.068µF
C109 C118: library part CMP-0012274-3, "CAP, Aluminum Polymer, 100 uF, 63 V, +/- 20%, 0.024 ohm, SMD, 2-Leads, Dia 10.5mm, Pin Spacing 8mm SMD", Cap_Case=10x12.7mm, MANUFACTURER=Nichicon, Supplier Part Number 1=493-13783-1-ND, Tolerance_%=20%, Value1="0.024 ohm", Value2=63V, ValueDisplayed=100uF
C110 C111 C112 C113 C114 C115 C116 C117 C119 C120 C121 C122 C123 C124 C125 C126 C127 C128: "CAP, CERM, 2.2 µF, 100 V, +/- 10%, X7R, 1206_190", Cap_Case=1206, MANUFACTURER=MuRata, Supplier Part Number 1=490-7209-1-ND, TempCo=X7R, Tolerance_%=10, Value1=Unknown, Value2=100V, ValueDisplayed=2.2µF
C129 C130: "CAP, CERM, 150 pF, 1000 V,+/- 5%, U2J, 1206", Cap_Case=1206, MANUFACTURER=MuRata, Supplier Part Number 1=490-4302-1-ND, TempCo=U2J, Tolerance_%=5, Value2=1000V, ValueDisplayed=150pF
C133: "CAP, CERM, 2.2 µF, 50 V,+/- 10%, X5R, 1206", Cap_Case=1206, MANUFACTURER=TDK, Supplier Part Number 1=445-14690-1-ND, TempCo=X5R, Tolerance_%=10, Value1="0.005887 ohm", Value2=50V, ValueDisplayed=2.2µF
C134: "CAP, CERM, 2.2 µF, 16 V,+/- 20%, X5R, 0603", Cap_Case=0603, MANUFACTURER="Wurth Elektronik", Supplier Part Number 1=732-7915-1-ND, TempCo=X5R, Tolerance_%=20, Value2=16V, ValueDisplayed=2.2µF
C135: "CAP, CERM, 2.2 µF, 6.3 V,+/- 10%, X5R, 0603", Cap_Case=0603, MANUFACTURER=Kemet, Supplier Part Number 1=399-3362-1-ND, TempCo=X5R, Tolerance_%=10, Value2=6.3V, ValueDisplayed=2.2µF
C136: "CAP, CERM, 2.2 µF, 16 V, +/- 10%, X7R, 1206", Cap_Case=1206, MANUFACTURER=Kemet, Supplier Part Number 1=80-C1206C225K4R, TempCo=X7R, Tolerance_%=10, Value1="0.009 ohm", Value2=16V, ValueDisplayed=2.2µF
C137 C138: "CAP, CERM, 100 pF, 50 V,+/- 5%, C0G/NP0, 0603", Cap_Case=0603, MANUFACTURER=AVX, Supplier Part Number 1=478-1175-1-ND, TempCo=C0G/NP0, Tolerance_%=5, Value1="0.119 ohm", Value2=50V, ValueDisplayed=100pF
C139: "CAP, CERM, 0.047 µF, 25 V,+/- 5%, X7R, 0603", Cap_Case=0603, MANUFACTURER=AVX, Supplier Part Number 1=478-3716-1-ND, TempCo=X7R, Tolerance_%=5, Value1="0.052 ohm", Value2=25V, ValueDisplayed=0.047µF
C140: "CAP, CERM, 0.1 µF, 100 V,+/- 10%, X7R, 1206", Cap_Case=1206, MANUFACTURER=MuRata, Supplier Part Number 1=490-3364-1-ND, TempCo=X7R, Tolerance_%=10, Value2=100V, ValueDisplayed=0.1µF
C141: library part UKL1V221KPD, "CAP, AL, 220 µF, 35 V, +/- 10%, TH", Cap_Case=10x20mm, MANUFACTURER=Wurth, Tolerance_%=10, Value2=35V, ValueDisplayed=220µF
C142: library part UHW1V681MPD6, "CAP, AL, 680 µF, 35 V, +/- 20%, 0.019 ohm, TH", Cap_Case=10x20, MANUFACTURER=Wurth, Tolerance_%=20, Value1="0.019 ohm", Value2=35V, ValueDisplayed=680µF
C145: "CAP, CERM, 47 pF, 50 V, +/- 1%, C0G/NP0, 0603", Cap_Case=0603, MANUFACTURER=MuRata, Supplier Part Number 1=490-9687-1-ND, TempCo=C0G/NP0, Tolerance_%=1, Value1=Unknown, Value2=50V, ValueDisplayed=47pF
C146: "CAP, CERM, 330 pF, 100 V,+/- 5%, X7R, 0603", Cap_Case=0603, MANUFACTURER=AVX, Supplier Part Number 1=478-3707-1-ND, TempCo=X7R, Tolerance_%=5, Value1="0.472 ohm", Value2=100V, ValueDisplayed=330pF
C147 C148 C149: "CAP, CERM, 4.7 µF, 16 V, +/- 10%, X5R, 0603", Cap_Case=0603, MANUFACTURER=MuRata, Supplier Part Number 1=490-10481-1-ND, TempCo=X5R, Tolerance_%=10, Value1=Unknown, Value2=16V, ValueDisplayed=4.7µF
C150: "CAP, CERM, 0.01 µF, 100 V,+/- 5%, X7R, 0603", Cap_Case=0603, MANUFACTURER=AVX, Supplier Part Number 1=478-3700-1-ND, TempCo=X7R, Tolerance_%=5, Value1="0.098 ohm", Value2=100V, ValueDisplayed=0.01µF
C151: "CAP, CERM, 0.1 µF, 16 V,+/- 5%, X7R, 0603", Cap_Case=0603, MANUFACTURER=AVX, Supplier Part Number 1=478-3726-1-ND, TempCo=X7R, Tolerance_%=5, Value1="0.039 ohm", Value2=16V, ValueDisplayed=0.1µF
C152: "CAP, CERM, 6800 pF, 100 V,+/- 10%, X7R, 0603", Cap_Case=0603, MANUFACTURER=AVX, Supplier Part Number 1=478-1204-1-ND, TempCo=X7R, Tolerance_%=10, Value1="0.115 ohm", Value2=100V, ValueDisplayed=6800pF
C153: "CAP, CERM, 2.2 pF, 50 V, +/- 11%, C0G/NP0, 0603", Cap_Case=0603, MANUFACTURER=AVX, Supplier Part Number 1=478-1155-1-ND, TempCo=C0G/NP0, Tolerance_%=11, Value1="1.033 ohm", Value2=50V, ValueDisplayed=2.2pF
C154: "CAP, CERM, 220 pF, 50 V, +/- 10%, X7R, 0603", Cap_Case=0603, MANUFACTURER=MuRata, Supplier Part Number 1=490-1483-1-ND, TempCo=X7R, Tolerance_%=10, Value1=Unknown, Value2=50V, ValueDisplayed=220pF
D100: "Diode, Schottky, 100 V, 0.25 A, SOD-123F", MANUFACTURER=Nexperia, Supplier Part Number 1=568-6016-1-ND, Value1=0.25A, Value2=0.85V
D101 D103 D108: "Diode, Switching, 100 V, 0.2 A, SOD-323", MANUFACTURER="Micro Commercial Components", Supplier Part Number 1=MMDL914-TPMSCT-ND, Value1=0.2A, Value2=1V
D102: "Diode, Schottky, 200 V, 2 A, SMB", MANUFACTURER=STMicroelectronics, Supplier Part Number 1=497-13718-1-ND, Value1=2A, Value2=0.8V
D104: "Diode, Ultrafast, 600 V, 1 A, AEC-Q101, SMAF", MANUFACTURER="Fairchild Semiconductor", Supplier Part Number 1=ES1JAFCT-ND, Value1=1A, Value2=1.7V
D105: library part CMP-0005762-2, "Diode, Zener, 33 V, 500 mW, SOD-123", MANUFACTURER="Diodes Inc.", Power_W=500mW, Supplier Part Number 1=MMSZ5257B-FDICT-ND, Value1=0.5W
D106: "Diode, Ultrafast, 100 V, 0.15 A, SOD-123", MANUFACTURER="Diodes Inc.", Supplier Part Number 1=1N4148W-FDICT-ND, Value1=0.15A, Value2=1.25V
D107: "Diode, Zener, 6.2 V, 500 mW, SOD-123", MANUFACTURER="Diodes Inc.", Power_W=0.5, Supplier Part Number 1=MMSZ5234B-FDICT-ND, Value1=0.5W
D109: "Diode, Zener, 20 V, 200 mW, SOD-323", MANUFACTURER="Diodes Inc.", Power_W=0.2, Supplier Part Number 1=MMSZ5250BS-FDICT-ND, Value1=0.2W
H100: library part CMP-0082193-1, "HEATSINK TO-220 W/PINS 1\" TALL", MANUFACTURER=Aavid, Supplier Part Number 1=HS403-ND
H101 H106 H107 H108: library part CMP-0003617-1, "Machine Screw, Round, #4-40 x 1/4, Nylon, Philips panhead", MANUFACTURER="B&F Fastener Supply", Supplier Part Number 1=H542-ND
J100: "Receptacle, 3x1, 5mm, R/A, TH", Color=Green, Current_A=24, MANUFACTURER="TE Connectivity", Supplier Part Number 1=A98356-ND, Voltage_V=300
J101 J102: library part CMP-0055471-1, "Terminal Block, 5.08 mm, 2x1, TH", Color=Green, Current_A=17.5A, MANUFACTURER="Phoenix Contact", Supplier Part Number 1=277-1263-ND, Voltage_V=400V
L100: library part CMP-0084749-1, "Inductor, Toroid, 0.0345 ohm, TH", MANUFACTURER="Renco Electronics", Value1="0.0345 ohm", Value2=A
Q100 Q101 Q102 Q104 Q105 Q107 Q108 Q109: library part CMP-0001075-2, "MOSFET, N-CH, 200 V, 36 A, PG-TDSON-8", Alternate Manufacturer=None, MANUFACTURER="Infineon Technologies", PartNumber=BSC350N20NSFD, Value1=0.03, Value2="22 nC"
Q103 Q106: library part CMP-0001179-3, "MOSFET N-CH 600V TO247-3", Alternate Manufacturer=None, MANUFACTURER="Infineon Technologies", PartNumber=IPW60R170CFD7
Q110: library part "FZT651TA, Zetex", "Transistor, NPN, 60 V, 3 A, SOT-223", MANUFACTURER=Zetex, Supplier Part Number 1=FZT651CT-ND, Value1="3 A", Value2=300
R100 R101 R102 R103 R108 R109 R111 R115: "RES, 3.0, 5%, 0.063 W, 0402", MANUFACTURER=Vishay-Dale, Power_W=0.063, Supplier Part Number 1=541-3.0JCT-ND, TempCo="200 ppm/C", Tolerance_%=5, Value1=5%, Value2=0.063W, Value_Code=3R00, ValueDisplayed=3.0
R104 R113: "RES, 10.0 k, 0.1%, 0.125 W, 0805", MANUFACTURER="Susumu Co Ltd", Power_W=0.125, Supplier Part Number 1=RG20P10.0KBCT-ND, TempCo="25 ppm/C", Tolerance_%=0.1, Value1=0.1%, Value2=0.125W, Value_Code=10k0, ValueDisplayed=10.0k
R105 R114: "RES, 10, 5%, 0.125 W, 0805", MANUFACTURER="Yageo America", Power_W=0.125, Supplier Part Number 1=311-10ARCT-ND, TempCo="200 ppm/C", Tolerance_%=5, Value1=5%, Value2=0.125W, Value_Code=10R0, ValueDisplayed=10
R106 R107: "RES, 49.9 k, 1%, 0.25 W, 1206", MANUFACTURER=Vishay-Dale, Power_W=0.25, Supplier Part Number 1=541-49.9KFCT-ND, TempCo="100 ppm/C", Tolerance_%=1, Value1=1%, Value2=0.25W, Value_Code=49k9, ValueDisplayed=49.9k
R110 R140: "RES, 51.1 k, 1%, 0.1 W, 0603", MANUFACTURER=Vishay-Dale, Power_W=0.1, Supplier Part Number 1=541-51.1KHCT-ND, TempCo="100 ppm/C", Tolerance_%=1, Value1=1%, Value2=0.1W, Value_Code=51k1, ValueDisplayed=51.1k
R112 R139: "RES, 10.0 k, 1%, 0.1 W, 0603", MANUFACTURER="Vishay Draloric", Power_W=0.1, Supplier Part Number 1=541-1784-1-ND, TempCo="100 ppm/C", Tolerance_%=1, Value1=1%, Value2=0.1W, Value_Code=10k0, ValueDisplayed=10.0k
R116: "RES, 0, 1%, 0.1 W, AEC-Q200 Grade 0, 0603", MANUFACTURER="Stackpole Electronics Inc", Power_W=0.1, Supplier Part Number 1=RMCF0603ZT0R00CT-ND, TempCo=ppm/C, Tolerance_%=1, Value1=1%, Value2=0.1W, Value_Code=0
R117: "RES, 2.2, 5%, 0.1 W, 0603", MANUFACTURER=Vishay-Dale, Power_W=0.1, Supplier Part Number 1=541-2.2GCT-ND, TempCo="200 ppm/C", Tolerance_%=5, Value1=5%, Value2=0.1W, Value_Code=2R20, ValueDisplayed=2.2
R118: "RES, 20.0, 1%, 0.1 W, 0603", MANUFACTURER=Vishay-Dale, Power_W=0.1, Supplier Part Number 1=541-20.0HCT-ND, TempCo="100 ppm/C", Tolerance_%=1, Value1=1%, Value2=0.1W, Value_Code=20R0, ValueDisplayed=20.0
R119 R126 R129: "RES, 4.99 M, 1%, 0.25 W, 1206", MANUFACTURER=Vishay-Dale, Power_W=0.25, Supplier Part Number 1=541-4.99MFCT-ND, TempCo="100 ppm/C", Tolerance_%=1, Value1=1%, Value2=0.25W, Value_Code=4M99, ValueDisplayed=4.99M
R120: "RES, 0, 5%, 0.75 W, AEC-Q200 Grade 0, 2010", MANUFACTURER=Vishay-Dale, Power_W=0.75, Supplier Part Number 1=541-0.0WCT-ND, TempCo=ppm/C, Tolerance_%=5, Value1=5%, Value2=0.75W, Value_Code=0000, ValueDisplayed=0
R121: "RES, 10.0 k, 1%, 0.1 W, 0603", MANUFACTURER=Panasonic, Power_W=0.1, Supplier Part Number 1=P10.0KHCT-ND, TempCo="100 ppm/C", Tolerance_%=1, Value1=1%, Value2=0.1W, Value_Code=10k0, ValueDisplayed=10.0k
R122: "RES, 1.58 k, 0.1%, 0.1 W, 0603", MANUFACTURER="Susumu Co Ltd", Power_W=0.1, Supplier Part Number 1=RG16P1.58KBCT-ND, TempCo="25 ppm/C", Value1=0.1%, Value2=0.1W, Value_Code=1k58, ValueDisplayed=1.58k
R123 R124 R125: "RES, 1.65 k, 1%, 0.25 W, 1206", MANUFACTURER=Vishay-Dale, Power_W=0.25, Supplier Part Number 1=541-1.65KFCT-ND, TempCo="100 ppm/C", Tolerance_%=1, Value1=1%, Value2=0.25W, Value_Code=1k65, ValueDisplayed=1.65k
R127: "RES, 6.04 k, 1%, 0.1 W, 0603", MANUFACTURER=Vishay-Dale, Power_W=0.1, Supplier Part Number 1=541-6.04KHCT-ND, TempCo="100 ppm/C", Tolerance_%=1, Value1=1%, Value2=0.1W, Value_Code=6k04, ValueDisplayed=6.04k
R128: "RES, 383 k, 1%, 0.1 W, 0603", MANUFACTURER=Vishay-Dale, Power_W=0.1, Supplier Part Number 1=541-383KHCT-ND, TempCo="100 ppm/C", Tolerance_%=1, Value1=1%, Value2=0.1W, Value_Code=383k
R130 R131: "RES, 10.0 k, 1%, 0.1 W, 0603", MANUFACTURER=Vishay-Dale, Power_W=0.1, Supplier Part Number 1=541-10.0KHCT-ND, TempCo="100 ppm/C", Tolerance_%=1, Value1=1%, Value2=0.1W, Value_Code=10k0, ValueDisplayed=10.0k
R132: "RES, 1.00 M, 1%, 0.25 W, 1206", MANUFACTURER=Vishay-Dale, Power_W=0.25, Supplier Part Number 1=541-1.00MFCT-ND, TempCo="100 ppm/C", Tolerance_%=1, Value1=1%, Value2=0.25W, Value_Code=1M00, ValueDisplayed=1.00M
R133: "RES, 590 k, 1%, 0.1 W, 0603", MANUFACTURER=Vishay-Dale, Power_W=0.1, Supplier Part Number 1=541-590KHCT-ND, TempCo="100 ppm/C", Tolerance_%=1, Value1=1%, Value2=0.1W, Value_Code=590k
R134: "RES, 20.0 k, 1%, 0.1 W, 0603", MANUFACTURER="Yageo America", Power_W=0.1, Supplier Part Number 1=311-20.0KHRCT-ND, TempCo="200 ppm/C", Tolerance_%=1, Value1=1%, Value2=0.1W, Value_Code=20k0, ValueDisplayed=20.0k
R135: "RES, 0, 1%, 0.5 W, 1206", MANUFACTURER=Keystone, Power_W=0.5, Supplier Part Number 1=36-5108CT-ND, TempCo=ppm/C, Tolerance_%=1, Value1=1%, Value2=0.5W, Value_Code=0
